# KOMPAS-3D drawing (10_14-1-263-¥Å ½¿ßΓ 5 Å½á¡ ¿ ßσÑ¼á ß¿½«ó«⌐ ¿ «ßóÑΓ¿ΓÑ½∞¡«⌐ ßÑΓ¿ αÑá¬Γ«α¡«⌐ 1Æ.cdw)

Views: Вид 1, Вид 2, Вид 3
Referenced files in C:\Program Files\ASCON\KOMPAS-3D V10\Sys\: Graphic.lcs
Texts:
  Стена
  Металлич. перекрытия
  Сэндвич-панели 100
  Блоки фундаментные 400
  Сэндвич-панели 150
  Текст на чертеже
  Размерные надписи
  Шероховатость
  Линия-выноска #1
  Линия-выноска #2
  Линия-выноска #3
  Отклонения формы и база
  Заголовок таблицы
  Ячейка таблицы
  Стрелка вида
  Обозначение изменения
  Фигурная скобка
  Номер узла
  Марка координационной оси
  VRCB
  Выносная надпись
  Обозначение узла
  Марка/позиционное обозначение с линией-выноской
  Марка/позиционное обозначение на линии
  Марка/позиционное обозначение без линии-выноски
  Normal
  txt
  Body Text
  heading 1
  Знак Знак Знак Знак Знак Знак
  Verdana
  Лит-Масса-Масштаб
  Материал-Предприятие
  MS Sans Serif
  Simplex
  Txt
  Title Specification
  Body Specification ( left align )
  Body Specificaton ( centered )
  Без имени
  Additional DXF text style 0
  Обычный
  Термин
  Список определений
  Адрес
  Цитаты
  Форматированный
  Courier New
  Z-конец формы
  Z-начало формы
  ТекстШаг1
  Денис
  heading 2
  AGOpus
  footer
  Title
  ООббыыччнныыйй
  Definition Term
  Definition List
  Address
  Blockquote
  Preformatted
  z-Bottom of Form
  z-Top of Form
  TXT
  header
  heading 8
  heading 3
  heading 6
  heading 7
  russ
  ТТееррммиинн
  ССппииссоокк ооппррееддееллеенниийй
  ААддрреесс
  ЦЦииттааттыы
  ФФооррммааттиирроовваанннныыйй
  Z-ккооннеецц ффооррммыы
  Z-ннааччааллоо ффооррммыы
  Абзац Знак
  heading 4
  heading 5
  heading 9
  GOST 2.304 type A
  rustxt
  цепи
  ссылки
  Маркировка
  Подпись в квадратике
  табл
  ЗОНА_привяз
  маркировка
  ГОСТ_МНЕ
  ESK - Обозначение
  текст переноса
  Тексты. 3,2
  Body Text 3
  клеммы, контакты
  тексты табл
  ISOCP
  HeliosLight
  Pa3
  Pa1
  Шрифт 2.5
  Заголовки
  RUSTXT
  NormalParagraphStyle
  Три с половиной
  style2
  Table Contents
  Table Heading
  Tahoma
  FR5
  надписи
  экспликация
  Здание
  Оси
  Примечания:
  Напряжение силовой и осветительной сети ~380/220 В.
  Нормируемая освещенность помещения принята согласно СНиП 23-05-95*.
  Заземление осветительной арматуры выполнить согласно ПУЭ.
  Выключатели установить у дверей со стороны ручки. Высота установки выключателей - 1,5м,
  розеток - 0,8 м.
  При установке штепсельных розеток необходимо выдержать расстояние от заземлённых частей
  оборудования не менее 0,5 м.
  Прокладка кабелей сети рабочего освещения и розеточной сети 220 В предусматривается в
  ПВХ трубах по стенам. Уровни прокладки кабелей уточняются на месте  монтажа.
  Ввод кабелей осуществляется через технологическое отверстие  в полу здания.
  Предусмотреть естественное освещение здания реакторной.
  Вентиляторы В1, В2 установлены на крыше.
  Система управления пуском вентиляторов В1, В2 выполнена с помощью многофункциональных
  цифровых  термостатов и температурных сенсоров. Монтажную схему силового щита А1 см.лист 7.
  Схему обогрева шкафа см. лист 8.
  Предусмотреть естественную вентиляцию, представленную в виде 4-х вентиляционных
  решеток размером 1500х1000, привязку решеток см. лист 3.
  Разводка кабелей и подключение всех устройств выполняется заводом изготовителем зданий
  реакторных.
  Шинки N и РЕ в шкафу А1 условно не показаны.
  Схема электроснабжения
  реакторной 1Т
  План освещения и вентиляции
  Поз.
  Кол.
  ед.,кг
  Приме-
  чание
  ГОСТ 50043.6-2000
  ГОСТ 51324.1-99
  ВКРм-6,3, исп.1
  ВКРм-12,5 исп.1
  LEDEL L-INDUSTRY NEW 12
  степень защиты IP65
  Розетка силовая, 2 модуля, DKC
  Переключатель серии Brava, DKC
  Вентилятор крышный, P=2,2 кВт
  Вентилятор крышный, P=4 кВт
  Светильник светодиодный
  Перечень основного оборудования
  (ЩСН 1 секция)
  QS1
  Acti 9
  iSW 4P
  QF1
  iC60N 2P
  хар-ка В
  QS1.4
  ВВГнг-LS 3х2,5
  ВВГнг-LS 5x6
  ВВГнг-LS 4x2,5
  ВВГнг-LS 4х2,5
  Освещение
  Розетка
  Вентилятор
  QF3
  iC60N 3P
  хар-ка С
  ВА 2129
  KM1
  iCT 4P
  KM2
  QF2
  QF4
  QF5
  Cхема
  управления
  пуском
  вентиляторов
  QF6
  Cхема обогрева
  шкафа
  собственных нужд
  POLYLINE_STYLE_0.73_RGB_0_0_0
  DIVIDE_RGB_0_0_0_SC_1_THICK_0.18
  DASHDOT1_RGB_0_0_0_SC_1_THICK_0.18
  осн 2
  K5LT_BASIC_RGB_0_0_255_THICK_0.3
  K5LT_AXLED_RGB_255_255_0_SC_1_THICK_0.09
  K5LT_REINFORCED_RGB_255_0_0_THICK_0.6
  POLYLINE_STYLE_0.30_RGB_0_0_255
  K5LT_THIN_RGB_0_0_0_THICK_0.09
  K5LT_THIN_INCLUDED_TO_HATCHING_RGB_0_0_0_THICK_0.09
  K5LT32769_RGB_0_0_0_THICK_0.09
  K5LT_THIN_RGB_0_0_0_THICK_0.13
  Стили документа
  Бетон
  Бетон 0
  Бетон 1
  Бетон 2
  Бетон 3
  План и схема силовой
  и осветительной сети в
  Н.контр.
  Разраб.
  Скахин
  Андреева
  Реконструкция ПС 110 кВ Опорная
  (замена трансформаторов 16МВА на 40МВА)
  Ведомость эскизного проекта
Dimensions and other numbers on the sheet: 10/14-1-263-ЭП; 5; 0; 7; 2,5; 3.5; 2.5; 1,8; 2,5 (контакты, клеммы); 2.5 курсив; 2,5_3; 3,2 (надписи); 3,5_01; 2,5_01; 3,5_tabl; 5_заголовок; 2,3_; 3,2_; 3,2_зона не привяз; 2,5 грязносинь; 5,0_белый_подчёркнутый; 3,2; 3.2 фиол; 3,5; 3,2 элементы; 3,2 линия; 3,2 таблица; 3.2 маркировка; 2.5_Э5_надписи; 2.5_Э5_ссылки; 2.5_кабель; 3.2; 2.5 надписи; 3,2 (Зоны); 3 и 5; 2; 3; 4; 1; 115; 570; 200; 4 кВт; 2,2 кВт; 4500; 4200; 1АВ-13; 77; 11.12; 10/14-1-ИОС7.1-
